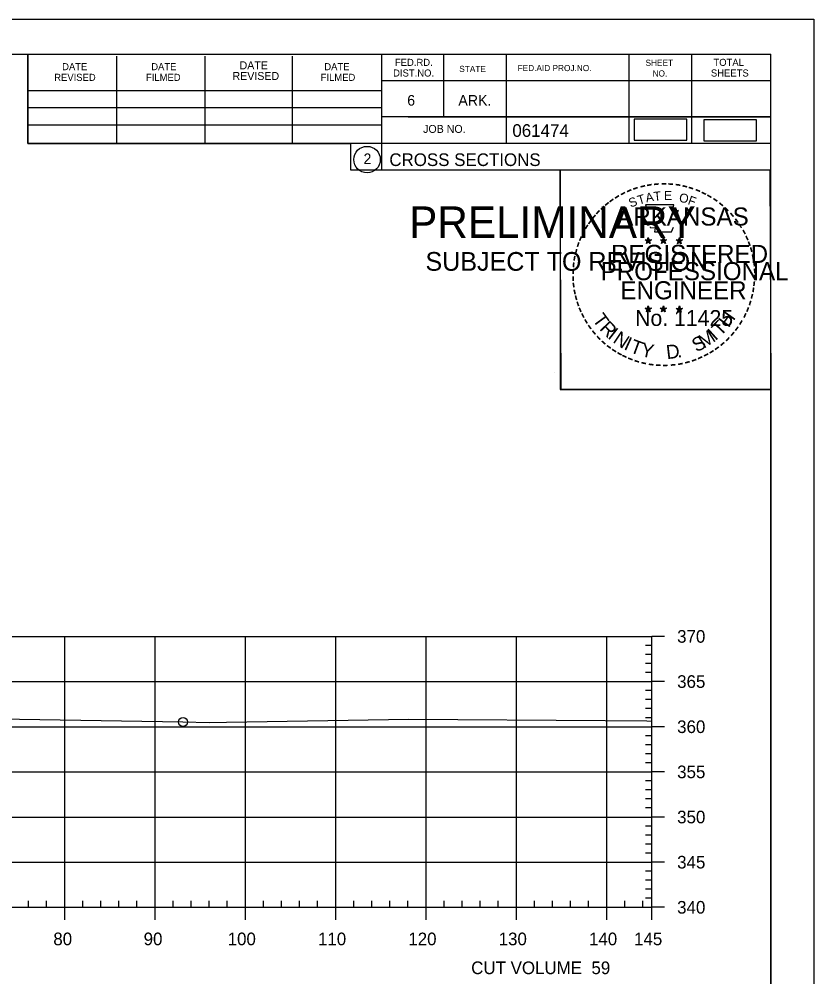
# Model space of a CAD drawing. Extents: x 1359801 to 1362404, y 372415 to 374228.
# Drawn here: x 1361278.7 to 1361366.6, y 373268.6 to 373374.6 of the extents above; entities that cross this region are included whole.
import ezdxf

# ---------------------------------------------------------------- set-up
doc = ezdxf.new("R2010")
doc.units = 0
for name, color, linetype in [('S_DRG_PT_SYM', 7, 'Continuous'), ('S_MAILBOX', 7, 'Continuous'), ('S_PRIMARY_CTL', 7, 'Continuous'), ('S_PRIMARY_CTL_ANNOT', 7, 'Continuous'), ('S_SHOULDER', 7, 'Continuous'), ('S_TELEPHONE_UTILITIES', 7, 'Continuous'), ('S_UNDERGROUND_CABLE', 7, 'Continuous'), ('S_UTL_PT_SYM', 7, 'Continuous'), ('S_WATER_UTILITIES', 7, 'Continuous')]:
    doc.layers.add(name, color=color, linetype=linetype)

msp = doc.modelspace()

# ---------------------------------------------------------------- linework, layer by layer
at = {"layer": 'S_DRG_PT_SYM'}
msp.add_lwpolyline([(1361224.32, 373294.55), (1361234.67, 373296.29), (1361237.1, 373296.59), (1361237.95, 373296.69), (1361239.4, 373296.74), (1361245.88, 373296.97), (1361250.85, 373297.01), (1361271.88, 373297.19), (1361296.79, 373296.79), (1361299.69, 373296.74), (1361301.63, 373296.78), (1361321.81, 373297.1), (1361343.54, 373296.96), (1361348.17, 373296.92), (1361348.71, 373296.89)], dxfattribs=at)
at = {"layer": 'S_MAILBOX'}
for p, q in [((1361058.71, 373306.26), (1361348.71, 373306.26)), ((1361283.71, 373276.26), (1361283.71, 373306.26)), ((1361293.71, 373276.26), (1361293.71, 373306.26)), ((1361303.71, 373276.26), (1361303.71, 373306.26)), ((1361313.71, 373276.26), (1361313.71, 373306.26)), ((1361323.71, 373276.26), (1361323.71, 373306.26)), ((1361333.71, 373276.26), (1361333.71, 373306.26)), ((1361343.71, 373276.26), (1361343.71, 373306.26)), ((1361348.71, 373276.26), (1361348.71, 373306.26)), ((1361058.71, 373301.26), (1361348.71, 373301.26)), ((1361058.71, 373296.26), (1361348.71, 373296.26)), ((1361058.71, 373291.26), (1361348.71, 373291.26)), ((1361058.71, 373286.26), (1361348.71, 373286.26)), ((1361058.71, 373281.26), (1361348.71, 373281.26)), ((1361058.71, 373276.26), (1361348.71, 373276.26))]:
    msp.add_line(p, q, dxfattribs=at)
at = {"layer": 'S_SHOULDER'}
for p, q in [((1361033.31, 373374.61), (1361366.64, 373374.61)), ((1361337.92, 373335.46), (1361337.92, 373335.46))]:
    msp.add_line(p, q, dxfattribs=at)
for points in [[(1361033.3, 373374.61), (1361366.64, 373374.61), (1361366.64, 373161.28), (1361033.3, 373161.28)], [(1361279.63, 373370.72), (1361279.63, 373360.84), (1361315.36, 373360.84), (1361315.36, 373357.92), (1361338.56, 373357.92), (1361338.56, 373333.59), (1361361.89, 373333.59), (1361361.89, 373165.26), (1361045.71, 373165.26), (1361045.71, 373370.72)], [(1361338.56, 373357.92), (1361361.77, 373357.92), (1361361.89, 373333.59), (1361338.68, 373333.59)]]:
    msp.add_lwpolyline(points, close=True, dxfattribs=at)
msp.add_circle((1361296.81, 373296.79), 0.5, dxfattribs=at)
at = {"layer": 'S_TELEPHONE_UTILITIES'}
for p, q in [((1361347.98, 373350.17), (1361348.32, 373350.06)), ((1361347.98, 373350.17), (1361348.23, 373350.13)), ((1361347.98, 373350.17), (1361348.21, 373350.05)), ((1361348.11, 373349.77), (1361348.32, 373350.06)), ((1361348.11, 373349.77), (1361348.23, 373350.01)), ((1361348.11, 373349.77), (1361348.32, 373349.98)), ((1361348.32, 373350.43), (1361348.28, 373350.18)), ((1361348.32, 373350.06), (1361348.32, 373350.43)), ((1361348.32, 373350.43), (1361348.37, 373350.18)), ((1361348.67, 373350.17), (1361348.32, 373350.06)), ((1361348.54, 373349.77), (1361348.32, 373350.06)), ((1361348.54, 373349.77), (1361348.32, 373349.98)), ((1361348.67, 373350.17), (1361348.39, 373350.13)), ((1361348.54, 373349.77), (1361348.4, 373350.06)), ((1361348.67, 373350.17), (1361348.47, 373350.07)), ((1361349.65, 373350.17), (1361349.99, 373350.06)), ((1361349.65, 373350.17), (1361349.9, 373350.13)), ((1361349.65, 373350.17), (1361349.88, 373350.05)), ((1361349.78, 373349.77), (1361349.99, 373350.06)), ((1361349.78, 373349.77), (1361349.9, 373350.01)), ((1361349.78, 373349.77), (1361349.99, 373349.98)), ((1361349.99, 373350.43), (1361349.95, 373350.18)), ((1361349.99, 373350.06), (1361349.99, 373350.43)), ((1361349.99, 373350.43), (1361350.04, 373350.18)), ((1361350.34, 373350.17), (1361349.99, 373350.06)), ((1361350.21, 373349.77), (1361349.99, 373350.06)), ((1361350.21, 373349.77), (1361349.99, 373349.98)), ((1361350.34, 373350.17), (1361350.06, 373350.13)), ((1361350.21, 373349.77), (1361350.07, 373350.06)), ((1361350.34, 373350.17), (1361350.14, 373350.07)), ((1361351.41, 373350.16), (1361351.76, 373350.05)), ((1361351.41, 373350.16), (1361351.66, 373350.12)), ((1361351.41, 373350.16), (1361351.65, 373350.04)), ((1361351.54, 373349.75), (1361351.76, 373350.05)), ((1361351.54, 373349.75), (1361351.67, 373350)), ((1361351.54, 373349.75), (1361351.76, 373349.97)), ((1361351.76, 373350.42), (1361351.72, 373350.16)), ((1361351.76, 373350.05), (1361351.76, 373350.42)), ((1361351.76, 373350.42), (1361351.81, 373350.17)), ((1361352.11, 373350.16), (1361351.76, 373350.05)), ((1361351.97, 373349.75), (1361351.76, 373350.05)), ((1361351.97, 373349.75), (1361351.76, 373349.97)), ((1361352.11, 373350.16), (1361351.82, 373350.11)), ((1361351.97, 373349.75), (1361351.83, 373350.05)), ((1361352.11, 373350.16), (1361351.9, 373350.06)), ((1361347.97, 373342.6), (1361348.32, 373342.49)), ((1361347.97, 373342.6), (1361348.22, 373342.56)), ((1361347.97, 373342.6), (1361348.21, 373342.48)), ((1361348.1, 373342.19), (1361348.32, 373342.49)), ((1361348.32, 373342.86), (1361348.28, 373342.6)), ((1361348.32, 373342.49), (1361348.32, 373342.86)), ((1361348.32, 373342.86), (1361348.37, 373342.61)), ((1361348.67, 373342.6), (1361348.32, 373342.49)), ((1361348.53, 373342.19), (1361348.32, 373342.49)), ((1361348.67, 373342.6), (1361348.38, 373342.55)), ((1361348.53, 373342.19), (1361348.4, 373342.48)), ((1361348.67, 373342.6), (1361348.46, 373342.5)), ((1361349.64, 373342.6), (1361349.99, 373342.49)), ((1361349.64, 373342.6), (1361349.89, 373342.56)), ((1361349.64, 373342.6), (1361349.88, 373342.48)), ((1361349.77, 373342.19), (1361349.99, 373342.49)), ((1361349.99, 373342.86), (1361349.95, 373342.6)), ((1361349.99, 373342.49), (1361349.99, 373342.86)), ((1361349.99, 373342.86), (1361350.04, 373342.61)), ((1361350.34, 373342.6), (1361349.99, 373342.49)), ((1361350.2, 373342.19), (1361349.99, 373342.49)), ((1361350.34, 373342.6), (1361350.05, 373342.55)), ((1361350.2, 373342.19), (1361350.07, 373342.48)), ((1361350.34, 373342.6), (1361350.13, 373342.5)), ((1361351.41, 373342.59), (1361351.76, 373342.48)), ((1361351.41, 373342.59), (1361351.66, 373342.55)), ((1361351.41, 373342.59), (1361351.64, 373342.47)), ((1361351.54, 373342.18), (1361351.76, 373342.48)), ((1361351.76, 373342.85), (1361351.72, 373342.59)), ((1361351.76, 373342.48), (1361351.76, 373342.85)), ((1361351.76, 373342.85), (1361351.81, 373342.6)), ((1361352.1, 373342.59), (1361351.76, 373342.48)), ((1361351.97, 373342.18), (1361351.76, 373342.48)), ((1361352.1, 373342.59), (1361351.82, 373342.54)), ((1361351.97, 373342.18), (1361351.83, 373342.47)), ((1361352.1, 373342.59), (1361351.9, 373342.49)), ((1361348.1, 373342.19), (1361348.23, 373342.44)), ((1361348.1, 373342.19), (1361348.32, 373342.41)), ((1361348.53, 373342.19), (1361348.32, 373342.41)), ((1361349.77, 373342.19), (1361349.9, 373342.44)), ((1361349.77, 373342.19), (1361349.99, 373342.41)), ((1361350.2, 373342.19), (1361349.99, 373342.41)), ((1361351.54, 373342.18), (1361351.67, 373342.43)), ((1361351.54, 373342.18), (1361351.75, 373342.4)), ((1361351.97, 373342.18), (1361351.75, 373342.4))]:
    msp.add_line(p, q, dxfattribs=at)
for points in [[(1361348.02, 373354.05), (1361348.29, 373353.23)], [(1361351.53, 373353.13), (1361351.67, 373353.41), (1361350.98, 373353.39), (1361351.13, 373354.05), (1361348.02, 373354.05)], [(1361348.51, 373351.63), (1361348.51, 373351.54), (1361349.07, 373351.52), (1361349.02, 373351.05), (1361350.89, 373351.05), (1361351.09, 373351.59)], [(1361348.32, 373350.43), (1361348.54, 373349.77), (1361347.98, 373350.17), (1361348.67, 373350.17), (1361348.11, 373349.77), (1361348.32, 373350.43)], [(1361349.99, 373350.43), (1361350.21, 373349.77), (1361349.65, 373350.17), (1361350.34, 373350.17), (1361349.78, 373349.77), (1361349.99, 373350.43)], [(1361351.76, 373350.42), (1361351.97, 373349.75), (1361351.41, 373350.16), (1361352.11, 373350.16), (1361351.54, 373349.75), (1361351.76, 373350.42)], [(1361348.32, 373342.86), (1361348.53, 373342.19), (1361347.97, 373342.6), (1361348.67, 373342.6), (1361348.1, 373342.19), (1361348.32, 373342.86)], [(1361349.99, 373342.86), (1361350.2, 373342.19), (1361349.64, 373342.6), (1361350.34, 373342.6), (1361349.77, 373342.19), (1361349.99, 373342.86)], [(1361351.76, 373342.85), (1361351.97, 373342.18), (1361351.41, 373342.59), (1361352.1, 373342.59), (1361351.54, 373342.18), (1361351.76, 373342.85)]]:
    msp.add_lwpolyline(points, dxfattribs=at)
for centre, radius in [((1361348.32, 373350.06), 0.172), ((1361348.32, 373350.06), 0.145), ((1361348.32, 373350.06), 0.116), ((1361348.32, 373350.06), 0.0991), ((1361348.32, 373350.06), 0.0747), ((1361348.32, 373350.06), 0.0495), ((1361348.32, 373350.06), 0.0296), ((1361349.99, 373350.06), 0.172), ((1361349.99, 373350.06), 0.145), ((1361349.99, 373350.06), 0.116), ((1361349.99, 373350.06), 0.0991), ((1361349.99, 373350.06), 0.0747), ((1361349.99, 373350.06), 0.0495), ((1361349.99, 373350.06), 0.0296), ((1361351.76, 373350.05), 0.172), ((1361351.76, 373350.05), 0.145), ((1361351.76, 373350.05), 0.116), ((1361351.76, 373350.05), 0.0991), ((1361351.76, 373350.05), 0.0747), ((1361351.76, 373350.05), 0.0495), ((1361351.76, 373350.05), 0.0296), ((1361348.32, 373342.49), 0.172), ((1361348.32, 373342.49), 0.145), ((1361348.32, 373342.49), 0.116), ((1361348.32, 373342.49), 0.0991), ((1361348.32, 373342.49), 0.0747), ((1361348.32, 373342.49), 0.0495), ((1361348.32, 373342.49), 0.0296), ((1361349.99, 373342.49), 0.172), ((1361349.99, 373342.49), 0.145), ((1361349.99, 373342.49), 0.116), ((1361349.99, 373342.49), 0.0991), ((1361349.99, 373342.49), 0.0747), ((1361349.99, 373342.49), 0.0495), ((1361349.99, 373342.49), 0.0296), ((1361351.76, 373342.48), 0.172), ((1361351.76, 373342.48), 0.145), ((1361351.76, 373342.48), 0.116), ((1361351.76, 373342.48), 0.0991), ((1361351.76, 373342.48), 0.0747), ((1361351.76, 373342.48), 0.0495), ((1361351.76, 373342.48), 0.0296)]:
    msp.add_circle(centre, radius, dxfattribs=at)
at = {"layer": 'S_UNDERGROUND_CABLE'}
for points in [[(1361346.74, 373361.22), (1361352.57, 373361.22), (1361352.57, 373363.53), (1361346.74, 373363.53)], [(1361354.47, 373361.14), (1361360.3, 373361.14), (1361360.3, 373363.45), (1361354.47, 373363.45)]]:
    msp.add_lwpolyline(points, close=True, dxfattribs=at)
at = {"layer": 'S_UTL_PT_SYM'}
for p, q in [((1361045.71, 373370.72), (1361361.89, 373370.72)), ((1361279.63, 373360.84), (1361279.63, 373370.72)), ((1361289.49, 373360.84), (1361289.49, 373370.52)), ((1361299.25, 373360.84), (1361299.25, 373370.52)), ((1361308.93, 373360.84), (1361308.93, 373370.52)), ((1361318.79, 373370.72), (1361318.79, 373357.92)), ((1361325.63, 373370.72), (1361325.63, 373363.78)), ((1361332.57, 373370.72), (1361332.57, 373360.84)), ((1361346.15, 373370.72), (1361346.15, 373360.84)), ((1361353.09, 373370.72), (1361353.09, 373360.84)), ((1361361.89, 373165.26), (1361361.89, 373370.72)), ((1361361.89, 373367.78), (1361318.79, 373367.78)), ((1361361.89, 373367.8), (1361361.89, 373367.8)), ((1361279.63, 373366.7), (1361318.79, 373366.7)), ((1361279.63, 373364.84), (1361318.79, 373364.84)), ((1361361.89, 373363.78), (1361318.79, 373363.78)), ((1361321.75, 373363.78), (1361361.89, 373363.78)), ((1361279.63, 373360.84), (1361279.63, 373362.9)), ((1361279.63, 373362.9), (1361318.79, 373362.9)), ((1361361.89, 373360.84), (1361279.63, 373360.84)), ((1361318.79, 373357.92), (1361361.89, 373357.92))]:
    msp.add_line(p, q, dxfattribs=at)
msp.add_circle((1361317.18, 373359.06), 1.47, dxfattribs=at)
at = {"layer": 'S_WATER_UTILITIES'}
for p, q in [((1361348.71, 373276.26), (1361348.71, 373306.26)), ((1361350.11, 373306.26), (1361348.71, 373306.26)), ((1361348.71, 373305.26), (1361348.01, 373305.26)), ((1361348.71, 373304.26), (1361348.01, 373304.26)), ((1361348.71, 373303.26), (1361348.01, 373303.26)), ((1361348.71, 373302.26), (1361348.01, 373302.26)), ((1361350.11, 373301.26), (1361348.71, 373301.26)), ((1361348.71, 373300.26), (1361348.01, 373300.26)), ((1361348.71, 373299.26), (1361348.01, 373299.26)), ((1361348.71, 373298.26), (1361348.01, 373298.26)), ((1361348.71, 373297.26), (1361348.01, 373297.26)), ((1361350.11, 373296.26), (1361348.71, 373296.26)), ((1361348.71, 373295.26), (1361348.01, 373295.26)), ((1361348.71, 373294.26), (1361348.01, 373294.26)), ((1361348.71, 373293.26), (1361348.01, 373293.26)), ((1361348.71, 373292.26), (1361348.01, 373292.26)), ((1361350.11, 373291.26), (1361348.71, 373291.26)), ((1361348.71, 373290.26), (1361348.01, 373290.26)), ((1361348.71, 373289.26), (1361348.01, 373289.26)), ((1361348.71, 373288.26), (1361348.01, 373288.26)), ((1361348.71, 373287.26), (1361348.01, 373287.26)), ((1361350.11, 373286.26), (1361348.71, 373286.26)), ((1361348.71, 373285.26), (1361348.01, 373285.26)), ((1361348.71, 373284.26), (1361348.01, 373284.26)), ((1361348.71, 373283.26), (1361348.01, 373283.26)), ((1361348.71, 373282.26), (1361348.01, 373282.26)), ((1361350.11, 373281.26), (1361348.71, 373281.26)), ((1361348.71, 373280.26), (1361348.01, 373280.26)), ((1361348.71, 373279.26), (1361348.01, 373279.26)), ((1361348.71, 373278.26), (1361348.01, 373278.26)), ((1361279.71, 373276.26), (1361279.71, 373276.96)), ((1361281.71, 373276.26), (1361281.71, 373276.96)), ((1361285.71, 373276.26), (1361285.71, 373276.96)), ((1361287.71, 373276.26), (1361287.71, 373276.96)), ((1361289.71, 373276.26), (1361289.71, 373276.96)), ((1361291.71, 373276.26), (1361291.71, 373276.96)), ((1361295.71, 373276.26), (1361295.71, 373276.96)), ((1361297.71, 373276.26), (1361297.71, 373276.96)), ((1361299.71, 373276.26), (1361299.71, 373276.96)), ((1361301.71, 373276.26), (1361301.71, 373276.96)), ((1361305.71, 373276.26), (1361305.71, 373276.96)), ((1361307.71, 373276.26), (1361307.71, 373276.96)), ((1361309.71, 373276.26), (1361309.71, 373276.96)), ((1361311.71, 373276.26), (1361311.71, 373276.96)), ((1361315.71, 373276.26), (1361315.71, 373276.96)), ((1361317.71, 373276.26), (1361317.71, 373276.96)), ((1361319.71, 373276.26), (1361319.71, 373276.96)), ((1361321.71, 373276.26), (1361321.71, 373276.96)), ((1361325.71, 373276.26), (1361325.71, 373276.96)), ((1361327.71, 373276.26), (1361327.71, 373276.96)), ((1361329.71, 373276.26), (1361329.71, 373276.96)), ((1361331.71, 373276.26), (1361331.71, 373276.96)), ((1361335.71, 373276.26), (1361335.71, 373276.96)), ((1361337.71, 373276.26), (1361337.71, 373276.96)), ((1361339.71, 373276.26), (1361339.71, 373276.96)), ((1361341.71, 373276.26), (1361341.71, 373276.96)), ((1361345.71, 373276.26), (1361345.71, 373276.96)), ((1361347.71, 373276.26), (1361347.71, 373276.96)), ((1361348.71, 373277.26), (1361348.01, 373277.26)), ((1361058.71, 373276.26), (1361348.71, 373276.26)), ((1361283.71, 373274.86), (1361283.71, 373276.26)), ((1361293.71, 373274.86), (1361293.71, 373276.26)), ((1361303.71, 373274.86), (1361303.71, 373276.26)), ((1361313.71, 373274.86), (1361313.71, 373276.26)), ((1361323.71, 373274.86), (1361323.71, 373276.26)), ((1361333.71, 373274.86), (1361333.71, 373276.26)), ((1361343.71, 373274.86), (1361343.71, 373276.26)), ((1361348.71, 373274.86), (1361348.71, 373276.26)), ((1361350.11, 373276.26), (1361348.71, 373276.26))]:
    msp.add_line(p, q, dxfattribs=at)

# ---------------------------------------------------------------- texts
at = {"layer": 'S_PRIMARY_CTL'}
for s, p in [('370', (1361351.51, 373305.56)), ('365', (1361351.51, 373300.56)), ('360', (1361351.51, 373295.56)), ('355', (1361351.51, 373290.56)), ('350', (1361351.51, 373285.56)), ('345', (1361351.51, 373280.56)), ('340', (1361351.51, 373275.56)), ('80', (1361282.45, 373272.06)), ('90', (1361292.45, 373272.06)), ('100', (1361301.75, 373272.06)), ('110', (1361311.75, 373272.06)), ('120', (1361321.75, 373272.06)), ('130', (1361331.75, 373272.06)), ('140', (1361341.75, 373272.06)), ('145', (1361346.74, 373272.06)), ('CUT VOLUME  59', (1361328.71, 373268.86))]:
    msp.add_text(s, height=1.4, dxfattribs=at).set_placement(p)
at = {"layer": 'S_PRIMARY_CTL_ANNOT'}
for s, height, p in [('PRELIMINARY', 3.5, (1361321.84, 373350.38)), ('DWB', 0.01, (1361322.59, 373352.23)), ('SUBJECT TO REVISION', 2.0751, (1361323.65, 373346.75))]:
    msp.add_text(s, height=height, rotation=360, dxfattribs=at).set_placement(p)
at = {"layer": 'S_SHOULDER'}
msp.add_text('+', height=0.1, dxfattribs=at).set_placement((1361348.13, 373296.87))
at = {"layer": 'S_TELEPHONE_UTILITIES'}
for s, height, rotation, p in [('-', 1.6, 13.6301, (1361347.51, 373355.42)), ('-', 1.6, 10.2193, (1361348.19, 373355.58)), ('-', 1.6, 5.8968, (1361348.92, 373355.69)), ('-', 1.6, 0.1862, (1361349.69, 373355.76)), ('-', 1.6, 357.743, (1361350.42, 373355.75)), ('-', 1.6, 352.1617, (1361351.16, 373355.7)), ('-', 1.6, 28.7918, (1361345.5, 373354.59)), ('-', 1.6, 24.3072, (1361346.13, 373354.91)), ('-', 1.6, 19.1761, (1361346.76, 373355.18)), ('T', 1, 16.4036, (1361347.28, 373354.06)), ('A', 1, 11.2132, (1361348.11, 373354.31)), ('T', 1, 6.0228, (1361348.96, 373354.48)), ('E', 1, 0.8323, (1361350.06, 373354.59)), ('O', 1, 350.4515, (1361351.67, 373354.38)), ('-', 1.6, 347.2049, (1361351.88, 373355.58)), ('-', 1.6, 342.3362, (1361352.51, 373355.43)), ('-', 1.6, 337.8551, (1361353.25, 373355.2)), ('-', 1.6, 334.1211, (1361353.88, 373354.93)), ('-', 1.6, 329.6409, (1361354.46, 373354.65)), ('-', 1.6, 38.9507, (1361343.85, 373353.45)), ('-', 1.6, 36.2317, (1361344.32, 373353.83)), ('-', 1.6, 34.0636, (1361344.9, 373354.22)), ('S', 1, 21.594, (1361346.37, 373353.73)), ('F', 1, 340.0707, (1361352.62, 373354.15)), ('-', 1.6, 325.8627, (1361355.1, 373354.29)), ('-', 1.6, 320.5297, (1361355.71, 373353.86)), ('-', 1.6, 48.423, (1361342.96, 373352.56)), ('-', 1.6, 42.9622, (1361343.41, 373353.03)), ('ARKANSAS', 2, 360, (1361344.87, 373351.76)), ('-', 1.6, 315.5786, (1361356.31, 373353.37)), ('-', 1.6, 309.8797, (1361356.88, 373352.82)), ('-', 1.6, 54.2325, (1361342.15, 373351.5)), ('-', 1.6, 50.6142, (1361342.56, 373352.07)), ('-', 1.6, 306.6522, (1361357.4, 373352.22)), ('-', 1.6, 62.8713, (1361341.51, 373350.36)), ('-', 1.6, 58.0706, (1361341.82, 373350.98)), ('-', 1.4, 303.6753, (1361357.89, 373351.65)), ('-', 1.6, 299.6684, (1361358.21, 373351.05)), ('-', 1.6, 72.3945, (1361341.03, 373349.12)), ('-', 1.6, 67.7743, (1361341.25, 373349.75)), ('DWB', 0.01, 360, (1361348.31, 373350.06)), ('DWB', 0.01, 360, (1361349.98, 373350.06)), ('DWB', 0.01, 360, (1361351.75, 373350.05)), ('-', 1.6, 294.6628, (1361358.53, 373350.44)), ('-', 1.6, 290.5728, (1361358.79, 373349.86)), ('-', 1.6, 75.461, (1361340.84, 373348.41)), ('REGISTERED', 2, 360, (1361344.19, 373347.62)), ('-', 1.6, 285.1233, (1361359.02, 373349.28)), ('-', 1.6, 81.2013, (1361340.7, 373347.69)), ('-', 1.6, 280.5493, (1361359.22, 373348.54)), ('-', 1.6, 89.0622, (1361340.6, 373346.3)), ('-', 1.6, 85.1863, (1361340.63, 373347)), ('PROFESSIONAL', 2, 360, (1361343.04, 373345.71)), ('-', 1.6, 276.5962, (1361359.39, 373347.77)), ('-', 1.6, 274.3301, (1361359.45, 373347.05)), ('-', 1.6, 94.1959, (1361340.64, 373345.58)), ('-', 1.6, 269.9407, (1361359.48, 373346.41)), ('-', 1.6, 98.9479, (1361340.71, 373344.91)), ('-', 1.6, 101.7149, (1361340.84, 373344.18)), ('ENGINEER', 2, 360, (1361345.23, 373343.59)), ('-', 1.6, 260.9953, (1361359.39, 373345.09)), ('-', 1.6, 263.5172, (1361359.46, 373345.75)), ('-', 1.6, 105.4578, (1361341.01, 373343.58)), ('-', 1.6, 255.7626, (1361359.28, 373344.42)), ('-', 1.6, 109.0874, (1361341.22, 373342.95)), ('-', 1.6, 114.0643, (1361341.48, 373342.35)), ('DWB', 0.01, 360, (1361348.31, 373342.49)), ('DWB', 0.01, 360, (1361349.98, 373342.49)), ('DWB', 0.01, 360, (1361351.74, 373342.48)), ('-', 1.6, 247.8887, (1361358.88, 373343.02)), ('-', 1.6, 252.8681, (1361359.1, 373343.7)), ('-', 1.6, 115.7289, (1361341.78, 373341.74)), ('-', 1.6, 120.4471, (1361342.14, 373341.15)), ('T', 1.54, 306.0406, (1361342.08, 373341.33)), ('No. 11425', 1.757, 360, (1361346.86, 373340.64)), ('H', 1.54, 54.6088, (1361357.2, 373340.36)), ('-', 1.6, 244.6197, (1361358.61, 373342.39)), ('-', 1.6, 125.8934, (1361342.54, 373340.59)), ('R', 1.54, 314.005, (1361342.84, 373340.28)), ('I', 1.54, 321.9694, (1361343.74, 373339.35)), ('T', 1.54, 46.6444, (1361356.31, 373339.42)), ('-', 1.6, 233.8452, (1361357.82, 373340.99)), ('-', 1.6, 239.0712, (1361358.22, 373341.64)), ('-', 1.6, 130.7181, (1361343, 373340.04)), ('-', 1.6, 134.2238, (1361343.52, 373339.49)), ('N', 1.54, 326.5002, (1361344.31, 373338.88)), ('I', 1.54, 335.3603, (1361345.52, 373338.09)), ('S', 1.54, 26.9312, (1361353.63, 373337.69)), ('M', 1.54, 32.6563, (1361354.46, 373338.1)), ('I', 1.54, 42.1136, (1361355.75, 373338.94)), ('-', 1.6, 225.7653, (1361356.91, 373339.86)), ('-', 1.6, 231.2538, (1361357.39, 373340.42)), ('-', 1.6, 138.9338, (1361344.04, 373339.03)), ('-', 1.6, 144.6463, (1361344.6, 373338.62)), ('T', 1.54, 339.8912, (1361346.18, 373337.76)), ('Y', 1.54, 347.8556, (1361347.4, 373337.32)), ('D', 1.54, 6.3969, (1361350.38, 373336.96)), ('-', 1.6, 215.7363, (1361355.84, 373338.88)), ('-', 1.6, 221.0851, (1361356.39, 373339.35)), ('-', 1.6, 148.0898, (1361345.16, 373338.25)), ('-', 1.6, 151.5704, (1361345.74, 373337.93)), ('-', 1.6, 154.6002, (1361346.26, 373337.68)), ('.', 1.54, 13.7642, (1361351.57, 373337.09)), ('-', 1.6, 204.2516, (1361354.12, 373337.83)), ('-', 1.6, 207.3568, (1361354.75, 373338.15)), ('-', 1.6, 212.2491, (1361355.3, 373338.49)), ('-', 1.6, 158.5612, (1361346.89, 373337.43)), ('-', 1.6, 162.7983, (1361347.57, 373337.21)), ('-', 1.6, 167.5555, (1361348.29, 373337.05)), ('-', 1.6, 173.1155, (1361349.06, 373336.94)), ('-', 1.6, 176.5183, (1361349.81, 373336.89)), ('-', 1.6, 181.5918, (1361350.55, 373336.9)), ('-', 1.6, 185.8167, (1361351.36, 373336.98)), ('-', 1.6, 191.2858, (1361352.1, 373337.11)), ('-', 1.6, 195.4743, (1361352.83, 373337.31)), ('-', 1.6, 200.7184, (1361353.5, 373337.55))]:
    msp.add_text(s, height=height, rotation=rotation, dxfattribs=at).set_placement(p)
at = {"layer": 'S_UTL_PT_SYM'}
for s, height, p in [('FED.RD.', 0.782, (1361320.27, 373369.44)), ('SHEET', 0.684, (1361348.01, 373369.44)), ('TOTAL', 0.782, (1361355.53, 373369.44)), ('DATE', 0.782, (1361283.43, 373368.96)), ('DATE', 0.782, (1361293.29, 373368.96)), ('DATE', 0.879, (1361303.07, 373369.06)), ('DATE', 0.782, (1361312.45, 373368.96)), ('DIST.NO.', 0.782, (1361320.07, 373368.26)), ('STATE', 0.684, (1361327.39, 373368.76)), ('FED.AID PROJ.NO.', 0.684, (1361333.85, 373368.86)), ('SHEETS', 0.782, (1361355.25, 373368.26)), ('REVISED', 0.782, (1361282.55, 373367.78)), ('FILMED', 0.782, (1361292.71, 373367.78)), ('REVISED', 0.879, (1361302.29, 373367.88)), ('FILMED', 0.782, (1361312.05, 373367.78)), ('NO.', 0.684, (1361348.79, 373368.26)), ('6', 1.17, (1361321.63, 373365.04)), ('ARK.', 1.172, (1361327.29, 373365.04)), ('JOB NO.', 0.879, (1361323.39, 373362.02)), ('061474', 1.4, (1361333.27, 373361.58)), ('2', 1.17, (1361316.79, 373358.57)), ('CROSS SECTIONS', 1.4, (1361319.65, 373358.35))]:
    msp.add_text(s, height=height, rotation=360, dxfattribs=at).set_placement(p)

doc.saveas('drawing.dxf')
